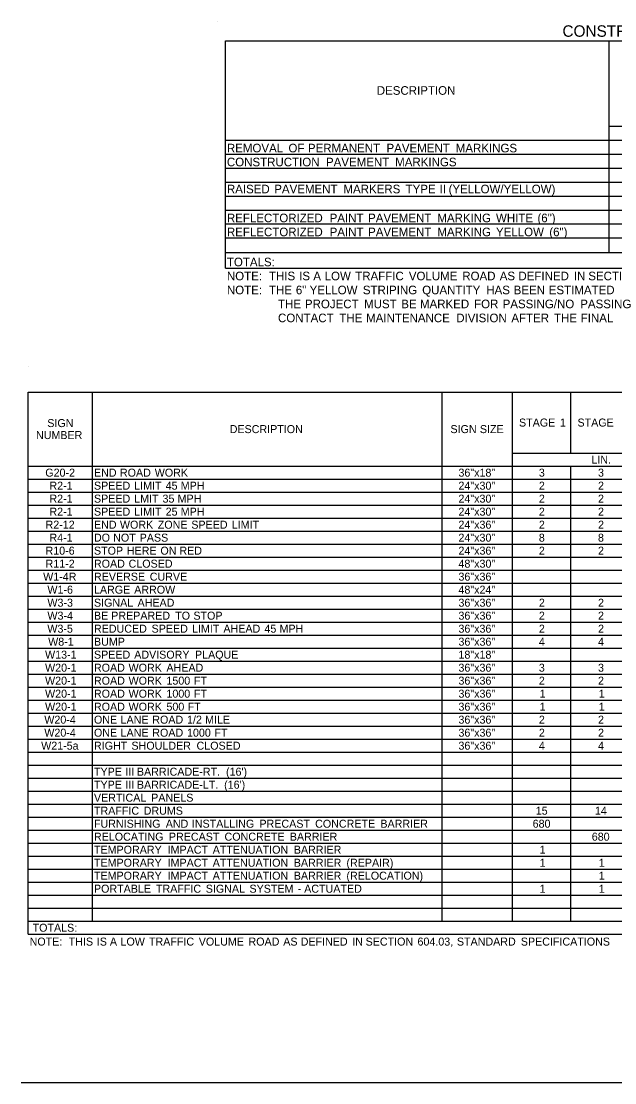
# Model space of a CAD drawing. Extents: x 1334738 to 1334853, y 402732 to 402753.
# Drawn here: x 1334737.56 to 1334747.92, y 402732.19 to 402750.69 of the extents above; entities that cross this region are included whole.
import ezdxf

# ---------------------------------------------------------------- set-up
doc = ezdxf.new("R2010")
doc.units = 0
doc.layers.add('Default', color=7, linetype='Continuous')
doc.layers.add('R_No Plot', color=7, linetype='Continuous')

msp = doc.modelspace()

# ---------------------------------------------------------------- linework, layer by layer
at = {"layer": 'Default'}
for p, q in [((1334740.981, 402750.692), (1334740.981, 402750.692)), ((1334741.127, 402750.351), (1334764.039, 402750.351)), ((1334741.127, 402746.39), (1334741.127, 402750.351)), ((1334741.127, 402746.39), (1334741.127, 402750.351)), ((1334747.818, 402746.658), (1334747.818, 402750.351)), ((1334747.818, 402748.864), (1334764.039, 402748.864)), ((1334741.127, 402748.62), (1334764.039, 402748.62)), ((1334747.818, 402746.658), (1334747.818, 402748.62)), ((1334741.127, 402748.376), (1334764.039, 402748.376)), ((1334741.127, 402748.133), (1334764.039, 402748.133)), ((1334741.127, 402747.889), (1334764.039, 402747.889)), ((1334741.127, 402747.645), (1334764.039, 402747.645)), ((1334741.127, 402747.401), (1334764.039, 402747.401)), ((1334741.127, 402747.158), (1334764.039, 402747.158)), ((1334741.127, 402746.914), (1334764.039, 402746.914)), ((1334741.127, 402746.658), (1334764.039, 402746.658)), ((1334741.127, 402746.39), (1334764.039, 402746.39)), ((1334737.688, 402744.681), (1334737.688, 402744.681)), ((1334737.688, 402744.228), (1334768.932, 402744.228)), ((1334737.688, 402734.777), (1334737.688, 402744.228)), ((1334738.81, 402735.003), (1334738.81, 402744.228)), ((1334744.907, 402735.003), (1334744.907, 402744.228)), ((1334746.131, 402735.003), (1334746.131, 402744.228)), ((1334747.151, 402743.163), (1334747.151, 402744.228)), ((1334746.131, 402743.163), (1334750.279, 402743.163)), ((1334737.688, 402742.936), (1334768.932, 402742.936)), ((1334738.81, 402736.816), (1334738.81, 402742.936)), ((1334744.907, 402736.816), (1334744.907, 402742.936)), ((1334746.131, 402736.59), (1334746.131, 402742.936)), ((1334747.151, 402735.003), (1334747.151, 402742.936)), ((1334737.688, 402742.709), (1334768.932, 402742.709)), ((1334737.688, 402742.483), (1334768.932, 402742.483)), ((1334737.688, 402742.256), (1334768.932, 402742.256)), ((1334737.688, 402742.029), (1334768.932, 402742.029)), ((1334737.688, 402741.803), (1334768.932, 402741.803)), ((1334737.688, 402741.576), (1334768.932, 402741.576)), ((1334737.688, 402741.349), (1334768.932, 402741.349)), ((1334737.688, 402741.123), (1334768.932, 402741.123)), ((1334737.688, 402740.896), (1334768.932, 402740.896)), ((1334737.688, 402740.669), (1334768.932, 402740.669)), ((1334737.688, 402740.443), (1334768.932, 402740.443)), ((1334737.688, 402740.216), (1334768.932, 402740.216)), ((1334737.688, 402739.99), (1334768.932, 402739.99)), ((1334737.688, 402739.763), (1334768.932, 402739.763)), ((1334737.688, 402739.536), (1334768.932, 402739.536)), ((1334737.688, 402739.31), (1334768.932, 402739.31)), ((1334737.688, 402739.083), (1334768.932, 402739.083)), ((1334737.688, 402738.856), (1334768.932, 402738.856)), ((1334737.688, 402738.63), (1334768.932, 402738.63)), ((1334737.688, 402738.403), (1334768.932, 402738.403)), ((1334737.688, 402738.176), (1334768.932, 402738.176)), ((1334737.688, 402737.95), (1334768.932, 402737.95)), ((1334737.688, 402737.723), (1334768.932, 402737.723)), ((1334737.688, 402737.496), (1334768.932, 402737.496)), ((1334737.688, 402737.27), (1334768.932, 402737.27)), ((1334737.688, 402737.043), (1334768.932, 402737.043)), ((1334737.688, 402736.816), (1334768.932, 402736.816)), ((1334737.688, 402736.59), (1334768.932, 402736.59)), ((1334744.907, 402736.59), (1334746.131, 402736.59)), ((1334746.131, 402736.59), (1334751.401, 402736.59)), ((1334737.688, 402736.363), (1334768.932, 402736.363)), ((1334737.688, 402736.136), (1334768.932, 402736.136)), ((1334737.688, 402735.91), (1334768.932, 402735.91)), ((1334737.688, 402735.683), (1334768.932, 402735.683)), ((1334737.688, 402735.456), (1334768.932, 402735.456)), ((1334738.81, 402735.003), (1334738.81, 402735.456)), ((1334744.907, 402735.003), (1334744.907, 402735.456)), ((1334737.688, 402735.23), (1334768.932, 402735.23)), ((1334738.81, 402735.23), (1334744.907, 402735.23)), ((1334744.907, 402735.23), (1334746.131, 402735.23)), ((1334746.131, 402735.23), (1334768.932, 402735.23)), ((1334746.131, 402735.003), (1334746.131, 402735.23)), ((1334737.688, 402735.003), (1334768.932, 402735.003)), ((1334738.81, 402735.003), (1334744.907, 402735.003)), ((1334744.907, 402735.003), (1334750.279, 402735.003)), ((1334737.688, 402734.777), (1334768.932, 402734.777))]:
    msp.add_line(p, q, dxfattribs=at)
at = {"layer": 'R_No Plot'}
msp.add_line((1334769.182, 402732.187), (1334737.564, 402732.187), dxfattribs=at)

# ---------------------------------------------------------------- texts
at = {"layer": 'Default'}
for s, height, p in [('CONSTRUCTION', 0.2, (1334747.003, 402750.421)), ('DESCRIPTION', 0.15, (1334743.765, 402749.41)), ('REMOVAL', 0.15, (1334741.151, 402748.406)), (' OF', 0.15, (1334742.169, 402748.406)), (' PERMANENT', 0.15, (1334742.508, 402748.406)), (' PAVEMENT', 0.15, (1334743.879, 402748.406)), (' MARKINGS', 0.15, (1334745.086, 402748.406)), ('CONSTRUCTION', 0.15, (1334741.151, 402748.163)), (' PAVEMENT', 0.15, (1334742.823, 402748.163)), (' MARKINGS', 0.15, (1334744.03, 402748.163)), ('RAISED', 0.15, (1334741.151, 402747.692)), (' PAVEMENT', 0.15, (1334741.921, 402747.692)), (' MARKERS', 0.15, (1334743.128, 402747.692)), (' TYPE', 0.15, (1334744.211, 402747.692)), (' II', 0.15, (1334744.806, 402747.692)), (' (YELLOW/YELLOW)', 0.15, (1334744.962, 402747.692)), ('REFLECTORIZED', 0.15, (1334741.151, 402747.188)), (' PAINT', 0.15, (1334742.887, 402747.188)), (' PAVEMENT', 0.15, (1334743.558, 402747.188)), (' MARKING', 0.15, (1334744.765, 402747.188)), (' WHITE', 0.15, (1334745.788, 402747.188)), (' (6")', 0.15, (1334746.511, 402747.188)), ('REFLECTORIZED', 0.15, (1334741.151, 402746.944)), (' PAINT', 0.15, (1334742.887, 402746.944)), (' PAVEMENT', 0.15, (1334743.558, 402746.944)), (' MARKING', 0.15, (1334744.765, 402746.944)), (' YELLOW', 0.15, (1334745.788, 402746.944)), (' (6")', 0.15, (1334746.718, 402746.944)), ('TOTALS:', 0.15, (1334741.151, 402746.42)), ('NOTE:', 0.15, (1334741.151, 402746.176)), ('  THIS', 0.15, (1334741.773, 402746.176)), (' IS', 0.15, (1334742.356, 402746.176)), (' A', 0.15, (1334742.602, 402746.176)), (' LOW', 0.15, (1334742.8, 402746.176)), (' TRAFFIC', 0.15, (1334743.333, 402746.176)), (' VOLUME', 0.15, (1334744.268, 402746.176)), (' ROAD', 0.15, (1334745.2, 402746.176)), (' AS', 0.15, (1334745.853, 402746.176)), (' DEFINED', 0.15, (1334746.179, 402746.176)), (' IN', 0.15, (1334747.146, 402746.176)), (' SECTION', 0.15, (1334747.397, 402746.176)), ('NOTE:', 0.15, (1334741.151, 402745.932)), ('  THE', 0.15, (1334741.773, 402745.932)), (' 6"', 0.15, (1334742.298, 402745.932)), (' YELLOW', 0.15, (1334742.537, 402745.932)), (' STRIPING', 0.15, (1334743.466, 402745.932)), (' QUANTITY', 0.15, (1334744.501, 402745.932)), (' HAS', 0.15, (1334745.618, 402745.932)), (' BEEN', 0.15, (1334746.096, 402745.932)), (' ESTIMATED', 0.15, (1334746.708, 402745.932)), ('  THE', 0.15, (1334741.931, 402745.689)), (' PROJECT', 0.15, (1334742.456, 402745.689)), (' MUST', 0.15, (1334743.488, 402745.689)), (' BE', 0.15, (1334744.136, 402745.689)), (' MARKED', 0.15, (1334744.462, 402745.689)), (' FOR', 0.15, (1334745.406, 402745.689)), (' PASSING/NO', 0.15, (1334745.904, 402745.689)), (' PASSING', 0.15, (1334747.257, 402745.689)), ('  CONTACT', 0.15, (1334741.931, 402745.445)), (' THE', 0.15, (1334743.057, 402745.445)), (' MAINTENANCE', 0.15, (1334743.523, 402745.445)), (' DIVISION', 0.15, (1334745.095, 402745.445)), (' AFTER', 0.15, (1334746.056, 402745.445)), (' THE', 0.15, (1334746.799, 402745.445)), (' FINAL', 0.15, (1334747.265, 402745.445)), ('SIGN', 0.1395, (1334738.019, 402743.617)), ('DESCRIPTION', 0.13948, (1334741.2, 402743.512)), ('SIGN', 0.1395, (1334745.05, 402743.512)), (' SIZE', 0.1395, (1334745.511, 402743.512)), ('STAGE', 0.1395, (1334746.245, 402743.626)), (' 1', 0.1395, (1334746.906, 402743.626)), ('STAGE', 0.1395, (1334747.265, 402743.626)), ('NUMBER', 0.1395, (1334737.822, 402743.408)), ('LIN.', 0.1395, (1334747.507, 402742.98)), ('G20-2', 0.1395, (1334737.984, 402742.753)), ('END', 0.1395, (1334738.833, 402742.753)), (' ROAD', 0.1395, (1334739.234, 402742.753)), (' WORK', 0.1395, (1334739.841, 402742.753)), ('36"x18"', 0.1395, (1334745.189, 402742.753)), ('3', 0.139, (1334746.591, 402742.753)), ('3', 0.139, (1334747.623, 402742.753)), ('R2-1', 0.1395, (1334738.056, 402742.526)), ('SPEED', 0.1395, (1334738.833, 402742.526)), (' LIMIT', 0.1395, (1334739.483, 402742.526)), (' 45', 0.1395, (1334740.031, 402742.526)), (' MPH', 0.1395, (1334740.294, 402742.526)), ('24"x30"', 0.1395, (1334745.189, 402742.526)), ('2', 0.139, (1334746.592, 402742.526)), ('2', 0.139, (1334747.623, 402742.526)), ('R2-1', 0.1395, (1334738.056, 402742.3)), ('SPEED', 0.1395, (1334738.833, 402742.3)), (' LMIT', 0.1395, (1334739.483, 402742.3)), (' 35', 0.1395, (1334739.977, 402742.3)), (' MPH', 0.1395, (1334740.24, 402742.3)), ('24"x30"', 0.1395, (1334745.189, 402742.3)), ('2', 0.139, (1334746.592, 402742.3)), ('2', 0.139, (1334747.623, 402742.3)), ('R2-1', 0.1395, (1334738.056, 402742.073)), ('SPEED', 0.1395, (1334738.833, 402742.073)), (' LIMIT', 0.1395, (1334739.483, 402742.073)), (' 25', 0.1395, (1334740.031, 402742.073)), (' MPH', 0.1395, (1334740.294, 402742.073)), ('24"x30"', 0.1395, (1334745.189, 402742.073)), ('2', 0.139, (1334746.592, 402742.073)), ('2', 0.139, (1334747.623, 402742.073)), ('R2-12', 0.1395, (1334737.989, 402741.846)), ('END', 0.1395, (1334738.833, 402741.846)), (' WORK', 0.1395, (1334739.234, 402741.846)), (' ZONE', 0.1395, (1334739.894, 402741.846)), (' SPEED', 0.1395, (1334740.479, 402741.846)), (' LIMIT', 0.1395, (1334741.184, 402741.846)), ('24"x36"', 0.1395, (1334745.189, 402741.846)), ('2', 0.139, (1334746.592, 402741.846)), ('2', 0.139, (1334747.623, 402741.846)), ('R4-1', 0.1395, (1334738.056, 402741.62)), ('DO', 0.1395, (1334738.833, 402741.62)), (' NOT', 0.1395, (1334739.116, 402741.62)), (' PASS', 0.1395, (1334739.578, 402741.62)), ('24"x30"', 0.1395, (1334745.189, 402741.62)), ('8', 0.139, (1334746.591, 402741.62)), ('8', 0.139, (1334747.622, 402741.62)), ('R10-6', 0.1395, (1334737.988, 402741.393)), ('STOP', 0.1395, (1334738.833, 402741.393)), (' HERE', 0.1395, (1334739.355, 402741.393)), (' ON', 0.1395, (1334739.94, 402741.393)), (' RED', 0.1395, (1334740.271, 402741.393)), ('24"x36"', 0.1395, (1334745.189, 402741.393)), ('2', 0.139, (1334746.592, 402741.393)), ('2', 0.139, (1334747.623, 402741.393)), ('R11-2', 0.1395, (1334737.989, 402741.166)), ('ROAD', 0.1395, (1334738.833, 402741.166)), (' CLOSED', 0.1395, (1334739.385, 402741.166)), ('48"x30"', 0.1395, (1334745.189, 402741.166)), ('W1-4R', 0.1395, (1334737.947, 402740.94)), ('REVERSE', 0.1395, (1334738.833, 402740.94)), (' CURVE', 0.1395, (1334739.754, 402740.94)), ('36"x36"', 0.1395, (1334745.189, 402740.94)), ('W1-6', 0.1395, (1334738.021, 402740.713)), ('LARGE', 0.1395, (1334738.833, 402740.713)), (' ARROW', 0.1395, (1334739.483, 402740.713)), ('48"x24"', 0.1395, (1334745.189, 402740.713)), ('W3-3', 0.1395, (1334738.021, 402740.486)), ('SIGNAL', 0.1395, (1334738.833, 402740.486)), (' AHEAD', 0.1395, (1334739.541, 402740.486)), ('36"x36"', 0.1395, (1334745.189, 402740.486)), ('2', 0.139, (1334746.592, 402740.486)), ('2', 0.139, (1334747.623, 402740.486)), ('W3-4', 0.1395, (1334738.021, 402740.26)), ('BE', 0.1395, (1334738.833, 402740.26)), (' PREPARED', 0.1395, (1334739.082, 402740.26)), (' TO', 0.1395, (1334740.198, 402740.26)), (' STOP', 0.1395, (1334740.515, 402740.26)), ('36"x36"', 0.1395, (1334745.189, 402740.26)), ('2', 0.139, (1334746.592, 402740.26)), ('2', 0.139, (1334747.623, 402740.26)), ('W3-5', 0.1395, (1334738.02, 402740.033)), ('REDUCED', 0.1395, (1334738.833, 402740.033)), (' SPEED', 0.1395, (1334739.786, 402740.033)), (' LIMIT', 0.1395, (1334740.491, 402740.033)), (' AHEAD', 0.1395, (1334741.039, 402740.033)), (' 45', 0.1395, (1334741.754, 402740.033)), (' MPH', 0.1395, (1334742.017, 402740.033)), ('36"x36"', 0.1395, (1334745.189, 402740.033)), ('2', 0.139, (1334746.592, 402740.033)), ('2', 0.139, (1334747.623, 402740.033)), ('W8-1', 0.1395, (1334738.034, 402739.806)), ('BUMP', 0.1395, (1334738.833, 402739.806)), ('36"x36"', 0.1395, (1334745.189, 402739.806)), ('4', 0.139, (1334746.592, 402739.806)), ('4', 0.139, (1334747.623, 402739.806)), ('W13-1', 0.1395, (1334737.98, 402739.58)), ('SPEED', 0.1395, (1334738.833, 402739.58)), (' ADVISORY', 0.1395, (1334739.483, 402739.58)), (' PLAQUE', 0.1395, (1334740.543, 402739.58)), ('18"x18"', 0.1395, (1334745.189, 402739.58)), ('W20-1', 0.1395, (1334737.98, 402739.353)), ('ROAD', 0.1395, (1334738.833, 402739.353)), (' WORK', 0.1395, (1334739.385, 402739.353)), (' AHEAD', 0.1395, (1334740.045, 402739.353)), ('36"x36"', 0.1395, (1334745.189, 402739.353)), ('3', 0.139, (1334746.591, 402739.353)), ('3', 0.139, (1334747.623, 402739.353)), ('W20-1', 0.1395, (1334737.98, 402739.127)), ('ROAD', 0.1395, (1334738.833, 402739.127)), (' WORK', 0.1395, (1334739.385, 402739.127)), (' 1500', 0.1395, (1334740.045, 402739.127)), (' FT', 0.1395, (1334740.524, 402739.127)), ('36"x36"', 0.1395, (1334745.189, 402739.127)), ('2', 0.139, (1334746.592, 402739.127)), ('2', 0.139, (1334747.623, 402739.127)), ('W20-1', 0.1395, (1334737.98, 402738.9)), ('ROAD', 0.1395, (1334738.833, 402738.9)), (' WORK', 0.1395, (1334739.385, 402738.9)), (' 1000', 0.1395, (1334740.045, 402738.9)), (' FT', 0.1395, (1334740.524, 402738.9)), ('36"x36"', 0.1395, (1334745.189, 402738.9)), ('1', 0.139, (1334746.605, 402738.9)), ('1', 0.139, (1334747.636, 402738.9)), ('W20-1', 0.1395, (1334737.98, 402738.673)), ('ROAD', 0.1395, (1334738.833, 402738.673)), (' WORK', 0.1395, (1334739.385, 402738.673)), (' 500', 0.1395, (1334740.045, 402738.673)), (' FT', 0.1395, (1334740.415, 402738.673)), ('36"x36"', 0.1395, (1334745.189, 402738.673)), ('1', 0.139, (1334746.605, 402738.673)), ('1', 0.139, (1334747.636, 402738.673)), ('W20-4', 0.1395, (1334737.967, 402738.447)), ('ONE', 0.1395, (1334738.833, 402738.447)), (' LANE', 0.1395, (1334739.245, 402738.447)), (' ROAD', 0.1395, (1334739.798, 402738.447)), (' 1/2', 0.1395, (1334740.404, 402738.447)), (' MILE', 0.1395, (1334740.719, 402738.447)), ('36"x36"', 0.1395, (1334745.189, 402738.447)), ('2', 0.139, (1334746.592, 402738.447)), ('2', 0.139, (1334747.623, 402738.447)), ('W20-4', 0.1395, (1334737.967, 402738.22)), ('ONE', 0.1395, (1334738.833, 402738.22)), (' LANE', 0.1395, (1334739.245, 402738.22)), (' ROAD', 0.1395, (1334739.798, 402738.22)), (' 1000', 0.1395, (1334740.404, 402738.22)), (' FT', 0.1395, (1334740.882, 402738.22)), ('36"x36"', 0.1395, (1334745.189, 402738.22)), ('2', 0.139, (1334746.592, 402738.22)), ('2', 0.139, (1334747.623, 402738.22)), ('W21-5a', 0.1395, (1334737.912, 402737.993)), ('RIGHT', 0.1395, (1334738.833, 402737.993)), (' SHOULDER', 0.1395, (1334739.435, 402737.993)), (' CLOSED', 0.1395, (1334740.57, 402737.993)), ('36"x36"', 0.1395, (1334745.189, 402737.993)), ('4', 0.139, (1334746.592, 402737.993)), ('4', 0.139, (1334747.623, 402737.993)), ('TYPE', 0.1395, (1334738.833, 402737.54)), (' III', 0.1395, (1334739.331, 402737.54)), (' BARRICADE-RT.', 0.13948, (1334739.53, 402737.54)), (" (16')", 0.1395, (1334741.084, 402737.54)), ('TYPE', 0.1395, (1334738.833, 402737.313)), (' III', 0.1395, (1334739.331, 402737.313)), (' BARRICADE-LT.', 0.13948, (1334739.53, 402737.313)), (" (16')", 0.1395, (1334741.051, 402737.313)), ('VERTICAL', 0.1395, (1334738.833, 402737.087)), (' PANELS', 0.1395, (1334739.779, 402737.087)), ('TRAFFIC', 0.1395, (1334738.833, 402736.86)), (' DRUMS', 0.1395, (1334739.648, 402736.86)), ('15', 0.1395, (1334746.537, 402736.86)), ('14', 0.1395, (1334747.569, 402736.86)), ('FURNISHING', 0.1395, (1334738.833, 402736.633)), (' AND', 0.1395, (1334740.033, 402736.633)), (' INSTALLING', 0.13948, (1334740.488, 402736.633)), (' PRECAST', 0.1395, (1334741.667, 402736.633)), (' CONCRETE', 0.1395, (1334742.638, 402736.633)), (' BARRIER', 0.1395, (1334743.776, 402736.633)), ('680', 0.1395, (1334746.483, 402736.633)), ('RELOCATING', 0.1395, (1334738.833, 402736.407)), (' PRECAST', 0.1395, (1334740.088, 402736.407)), (' CONCRETE', 0.1395, (1334741.058, 402736.407)), (' BARRIER', 0.1395, (1334742.196, 402736.407)), ('680', 0.1395, (1334747.514, 402736.407)), ('TEMPORARY', 0.1395, (1334738.833, 402736.18)), (' IMPACT', 0.1395, (1334740.066, 402736.18)), (' ATTENUATION', 0.13948, (1334740.852, 402736.18)), (' BARRIER', 0.1395, (1334742.266, 402736.18)), ('1', 0.139, (1334746.605, 402736.18)), ('TEMPORARY', 0.1395, (1334738.833, 402735.953)), (' IMPACT', 0.1395, (1334740.066, 402735.953)), (' ATTENUATION', 0.13948, (1334740.852, 402735.953)), (' BARRIER', 0.1395, (1334742.266, 402735.953)), (' (REPAIR)', 0.1395, (1334743.184, 402735.953)), ('1', 0.139, (1334746.605, 402735.953)), ('1', 0.139, (1334747.636, 402735.953)), ('TEMPORARY', 0.1395, (1334738.833, 402735.727)), (' IMPACT', 0.1395, (1334740.066, 402735.727)), (' ATTENUATION', 0.13948, (1334740.852, 402735.727)), (' BARRIER', 0.1395, (1334742.266, 402735.727)), (' (RELOCATION)', 0.13948, (1334743.184, 402735.727)), ('1', 0.139, (1334747.636, 402735.727)), ('PORTABLE', 0.1395, (1334738.833, 402735.5)), (' TRAFFIC', 0.1395, (1334739.862, 402735.5)), (' SIGNAL', 0.1395, (1334740.731, 402735.5)), (' SYSTEM', 0.1395, (1334741.493, 402735.5)), (' ACTUATED', 0.1395, (1334742.447, 402735.5)), (' -', 0.1395, (1334742.334, 402735.5)), ('1', 0.139, (1334746.605, 402735.5)), ('1', 0.139, (1334747.636, 402735.5)), (' TOTALS:', 0.1395, (1334737.711, 402734.82)), ('NOTE:', 0.1395, (1334737.711, 402734.578)), ('  THIS', 0.1395, (1334738.289, 402734.578)), (' IS', 0.1395, (1334738.831, 402734.578)), (' A', 0.1395, (1334739.059, 402734.578)), (' LOW', 0.1395, (1334739.244, 402734.578)), (' TRAFFIC', 0.1395, (1334739.74, 402734.578)), (' VOLUME', 0.1395, (1334740.609, 402734.578)), (' ROAD', 0.1395, (1334741.476, 402734.578)), (' AS', 0.1395, (1334742.082, 402734.578)), (' DEFINED', 0.1395, (1334742.386, 402734.578)), (' IN', 0.1395, (1334743.285, 402734.578)), (' SECTION', 0.1395, (1334743.518, 402734.578)), (' 604.03,', 0.1395, (1334744.423, 402734.578)), (' STANDARD', 0.1395, (1334745.11, 402734.578)), (' SPECIFICATIONS', 0.13948, (1334746.225, 402734.578))]:
    msp.add_text(s, height=height, dxfattribs=at).set_placement(p)

doc.saveas('drawing.dxf')
